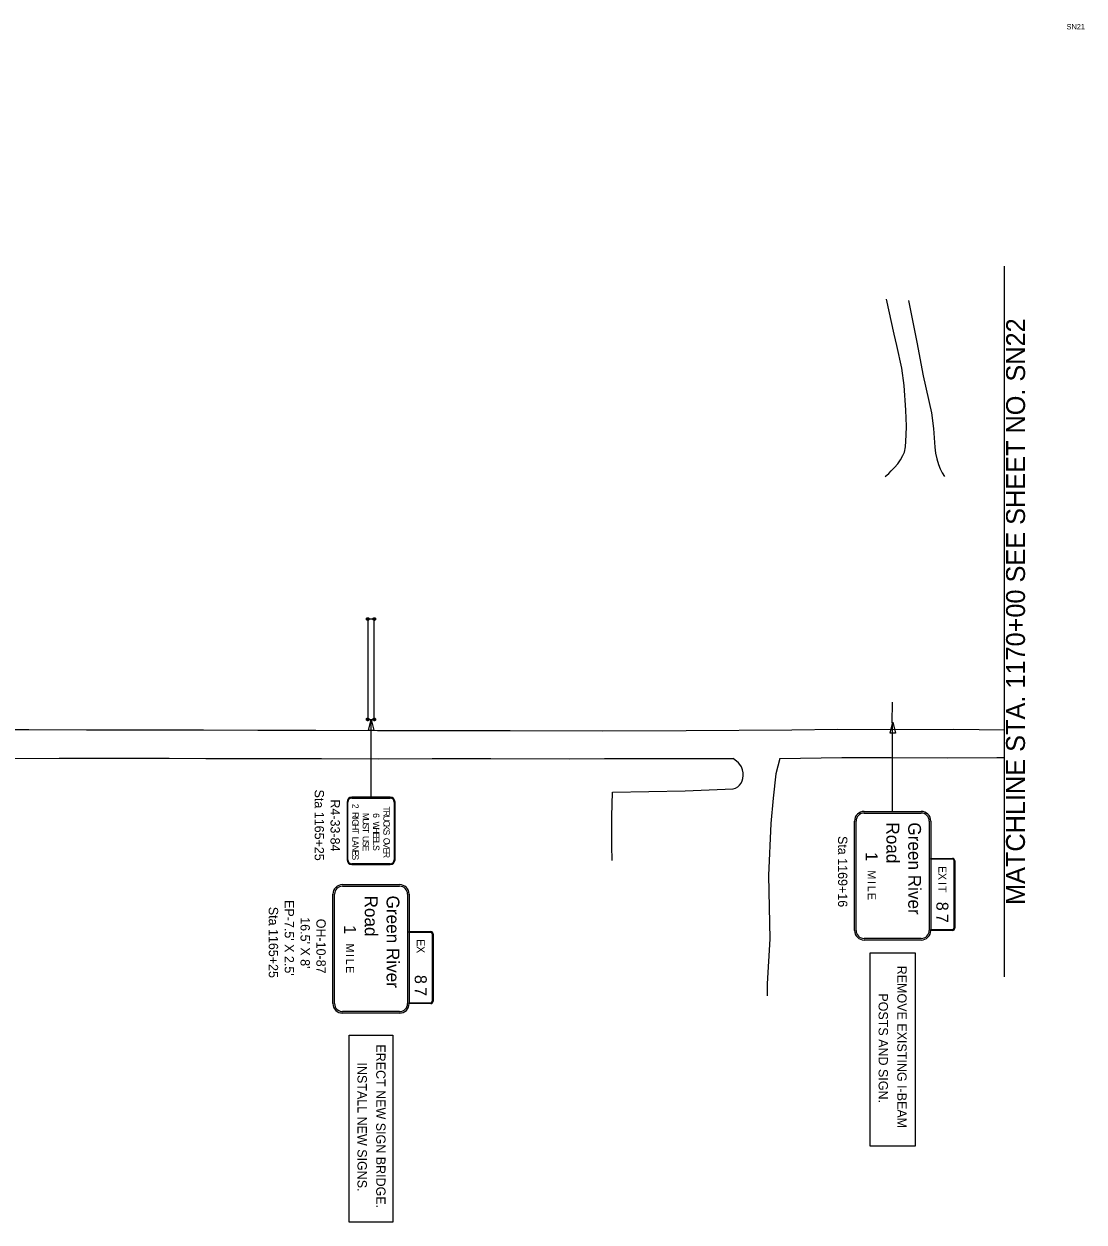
# Model space of a CAD drawing. Extents: x 1738684 to 1740273, y 1165576 to 1166490.
# Drawn here: x 1739479 to 1740273, y 1165592 to 1166490 of the extents above; entities that cross this region are included whole.
import ezdxf

# ---------------------------------------------------------------- set-up
doc = ezdxf.new("R2010")
doc.units = 0
for name, color, linetype in [('RD_EX_Driveway', 7, 'Continuous'), ('RD_EX_Road', 7, 'Continuous'), ('RD_SHT_MatchLine', 7, 'Continuous'), ('RD_SHT_TX', 7, 'Continuous'), ('SN_P_Signs', 7, 'Continuous')]:
    doc.layers.add(name, color=color, linetype=linetype)

msp = doc.modelspace()

# ---------------------------------------------------------------- linework, layer by layer
at = {"layer": 'RD_EX_Driveway'}
for points in [[(1740124.3, 1166150.79), (1740126.88, 1166153.21), (1740128.62, 1166155.12), (1740131.31, 1166157.59), (1740133.71, 1166160.34), (1740135.8, 1166163.33), (1740137.56, 1166166.52), (1740138.63, 1166169), (1740139.39, 1166173.21), (1740139.88, 1166181.79), (1740140.08, 1166188.6), (1740139.67, 1166200.6), (1740138.43, 1166219.04), (1740136.79, 1166232.06), (1740133.05, 1166248.97), (1740130.97, 1166257.45), (1740125.25, 1166283.83)], [(1740141.68, 1166282.68), (1740147.89, 1166251.53), (1740152.64, 1166226.36), (1740158.84, 1166198.47), (1740160.4, 1166186.89), (1740161.51, 1166172.79), (1740161.99, 1166168.39), (1740162.85, 1166164.05), (1740164.1, 1166159.81), (1740165.34, 1166156.58), (1740166.9, 1166153.51), (1740168.71, 1166150.79)]]:
    msp.add_lwpolyline(points, dxfattribs=at)
at = {"layer": 'RD_EX_Road'}
for points in [[(1739438.73, 1165961.23), (1739482.2, 1165961.17), (1739525.52, 1165960.92), (1739569.49, 1165960.93), (1739613.16, 1165961.06), (1739653.93, 1165960.81), (1739697.41, 1165960.69), (1739743.53, 1165960.46), (1739801.27, 1165960.46), (1739843.11, 1165960.51), (1739912.34, 1165960.31), (1739974.95, 1165960.36), (1740054.2, 1165960.92), (1740088.36, 1165961.42), (1740131.15, 1165961.18), (1740175.74, 1165961.39), (1740213.73, 1165961.1)], [(1739459.48, 1165939.5), (1739504.95, 1165939.79), (1739528.09, 1165939.84), (1739548.18, 1165939.78), (1739587.4, 1165939.65), (1739614.91, 1165939.48), (1739637.66, 1165939.49), (1739674.67, 1165939.42), (1739701.63, 1165939.38), (1739744.03, 1165939.26), (1739784.65, 1165939.45), (1739828.6, 1165939.52), (1739887.88, 1165939.19), (1739913.86, 1165939.4), (1739956.57, 1165939.5), (1740000.31, 1165939.39), (1740010.26, 1165939.42)], [(1739919.5, 1165863.11), (1739919.27, 1165874.13), (1739919.22, 1165895.91), (1739919.69, 1165914.25), (1739974.21, 1165915.27), (1740010.18, 1165916.63), (1740012, 1165917.21), (1740013.66, 1165918.14), (1740015.09, 1165919.4), (1740016.24, 1165920.92), (1740017.05, 1165922.65), (1740017.48, 1165924.41), (1740017.8, 1165926.63), (1740017.73, 1165928.87), (1740017.28, 1165931.06), (1740016.44, 1165933.14), (1740015.25, 1165935.04), (1740014.34, 1165936.13), (1740010.26, 1165939.42)], [(1740045.27, 1165939.54), (1740042.13, 1165928), (1740040.27, 1165909.67), (1740038.6, 1165890.89), (1740036.74, 1165851.82), (1740037.76, 1165804.35), (1740035.82, 1165770.69), (1740035.65, 1165761.7)], [(1740045.27, 1165939.54), (1740091.68, 1165940.16), (1740128.58, 1165940.15), (1740170.89, 1165940.11), (1740207.97, 1165940.27), (1740213.73, 1165940.27)]]:
    msp.add_lwpolyline(points, dxfattribs=at)
at = {"layer": 'RD_SHT_MatchLine'}
msp.add_lwpolyline([(1740213.73, 1165775.92), (1740213.73, 1166044.04), (1740213.73, 1166308.6)], dxfattribs=at)
at = {"layer": 'SN_P_Signs'}
for p, q in [((1739735.55, 1166044.75), (1739736.96, 1166043.33)), ((1739735.55, 1166043.34), (1739736.96, 1166044.75)), ((1739741.21, 1166044.04), (1739736.26, 1166044.04)), ((1739736.26, 1166044.04), (1739736.26, 1165968.79)), ((1739740.51, 1166044.75), (1739741.92, 1166043.33)), ((1739740.51, 1166043.34), (1739741.92, 1166044.75)), ((1739741.21, 1165968.79), (1739741.21, 1166044.04)), ((1740129.46, 1165966.18), (1740129.66, 1165981.72)), ((1739735.55, 1165969.5), (1739736.96, 1165968.08)), ((1739735.55, 1165968.09), (1739736.96, 1165969.5)), ((1739736.26, 1165968.79), (1739741.21, 1165968.79)), ((1739738.73, 1165910.44), (1739738.73, 1165968.79)), ((1739740.51, 1165969.5), (1739741.92, 1165968.08)), ((1739740.51, 1165968.09), (1739741.92, 1165969.5)), ((1740129.82, 1165899.83), (1740129.82, 1165966.65)), ((1740113.01, 1165648.89), (1740113.01, 1165793.91)), ((1740113.01, 1165793.91), (1740146.63, 1165793.91)), ((1740146.63, 1165793.91), (1740146.63, 1165648.89)), ((1739722.33, 1165592.05), (1739722.33, 1165732)), ((1739722.33, 1165732), (1739755.14, 1165732)), ((1739755.14, 1165732), (1739755.14, 1165592.05)), ((1740146.63, 1165648.89), (1740113.01, 1165648.89)), ((1739755.14, 1165592.05), (1739722.33, 1165592.05))]:
    msp.add_line(p, q, dxfattribs=at)
for points in [[(1739736.26, 1166043.04), (1739736.09, 1166043.06), (1739735.93, 1166043.1), (1739735.77, 1166043.16), (1739735.64, 1166043.26), (1739735.51, 1166043.37), (1739735.41, 1166043.5), (1739735.34, 1166043.65), (1739735.28, 1166043.81), (1739735.26, 1166043.97), (1739735.26, 1166044.14), (1739735.29, 1166044.31), (1739735.35, 1166044.46), (1739735.43, 1166044.61), (1739735.54, 1166044.74), (1739735.66, 1166044.85), (1739735.81, 1166044.93), (1739735.96, 1166045), (1739736.12, 1166045.03), (1739736.26, 1166045.04)], [(1739736.26, 1166045.04), (1739736.42, 1166045.03), (1739736.59, 1166044.99), (1739736.74, 1166044.92), (1739736.88, 1166044.83), (1739737, 1166044.71), (1739737.1, 1166044.58), (1739737.18, 1166044.43), (1739737.23, 1166044.27), (1739737.25, 1166044.11), (1739737.25, 1166043.94), (1739737.22, 1166043.78), (1739737.16, 1166043.62), (1739737.08, 1166043.47), (1739736.98, 1166043.35), (1739736.85, 1166043.24), (1739736.71, 1166043.15), (1739736.55, 1166043.09), (1739736.39, 1166043.05), (1739736.26, 1166043.04)], [(1739741.21, 1166043.04), (1739741.05, 1166043.06), (1739740.88, 1166043.1), (1739740.73, 1166043.16), (1739740.59, 1166043.26), (1739740.47, 1166043.37), (1739740.37, 1166043.5), (1739740.29, 1166043.65), (1739740.24, 1166043.81), (1739740.21, 1166043.97), (1739740.22, 1166044.14), (1739740.25, 1166044.31), (1739740.31, 1166044.46), (1739740.39, 1166044.61), (1739740.49, 1166044.74), (1739740.62, 1166044.85), (1739740.76, 1166044.93), (1739740.92, 1166045), (1739741.08, 1166045.03), (1739741.21, 1166045.04)], [(1739741.21, 1166045.04), (1739741.38, 1166045.03), (1739741.54, 1166044.99), (1739741.69, 1166044.92), (1739741.83, 1166044.83), (1739741.95, 1166044.71), (1739742.06, 1166044.58), (1739742.13, 1166044.43), (1739742.19, 1166044.27), (1739742.21, 1166044.11), (1739742.21, 1166043.94), (1739742.18, 1166043.78), (1739742.12, 1166043.62), (1739742.04, 1166043.47), (1739741.93, 1166043.35), (1739741.8, 1166043.24), (1739741.66, 1166043.15), (1739741.51, 1166043.09), (1739741.35, 1166043.05), (1739741.21, 1166043.04)], [(1739736.26, 1165967.79), (1739736.09, 1165967.81), (1739735.93, 1165967.85), (1739735.77, 1165967.91), (1739735.64, 1165968.01), (1739735.51, 1165968.12), (1739735.41, 1165968.25), (1739735.34, 1165968.4), (1739735.28, 1165968.56), (1739735.26, 1165968.72), (1739735.26, 1165968.89), (1739735.29, 1165969.06), (1739735.35, 1165969.21), (1739735.43, 1165969.36), (1739735.54, 1165969.49), (1739735.66, 1165969.6), (1739735.81, 1165969.68), (1739735.96, 1165969.75), (1739736.12, 1165969.78), (1739736.26, 1165969.79)], [(1739736.26, 1165969.79), (1739736.42, 1165969.78), (1739736.59, 1165969.74), (1739736.74, 1165969.67), (1739736.88, 1165969.58), (1739737, 1165969.46), (1739737.1, 1165969.33), (1739737.18, 1165969.18), (1739737.23, 1165969.02), (1739737.25, 1165968.86), (1739737.25, 1165968.69), (1739737.22, 1165968.53), (1739737.16, 1165968.37), (1739737.08, 1165968.22), (1739736.98, 1165968.1), (1739736.85, 1165967.99), (1739736.71, 1165967.9), (1739736.55, 1165967.84), (1739736.39, 1165967.8), (1739736.26, 1165967.79)], [(1739741.21, 1165967.79), (1739741.05, 1165967.81), (1739740.88, 1165967.85), (1739740.73, 1165967.91), (1739740.59, 1165968.01), (1739740.47, 1165968.12), (1739740.37, 1165968.25), (1739740.29, 1165968.4), (1739740.24, 1165968.56), (1739740.21, 1165968.72), (1739740.22, 1165968.89), (1739740.25, 1165969.06), (1739740.31, 1165969.21), (1739740.39, 1165969.36), (1739740.49, 1165969.49), (1739740.62, 1165969.6), (1739740.76, 1165969.68), (1739740.92, 1165969.75), (1739741.08, 1165969.78), (1739741.21, 1165969.79)], [(1739741.21, 1165969.79), (1739741.38, 1165969.78), (1739741.54, 1165969.74), (1739741.69, 1165969.67), (1739741.83, 1165969.58), (1739741.95, 1165969.46), (1739742.06, 1165969.33), (1739742.13, 1165969.18), (1739742.19, 1165969.02), (1739742.21, 1165968.86), (1739742.21, 1165968.69), (1739742.18, 1165968.53), (1739742.12, 1165968.37), (1739742.04, 1165968.22), (1739741.93, 1165968.1), (1739741.8, 1165967.99), (1739741.66, 1165967.9), (1739741.51, 1165967.84), (1739741.35, 1165967.8), (1739741.21, 1165967.79)], [(1739720.73, 1165906.84), (1739720.73, 1165863.64)], [(1739721.33, 1165863.64), (1739721.33, 1165906.84)], [(1739753.13, 1165910.44), (1739724.33, 1165910.44)], [(1739724.33, 1165909.84), (1739753.13, 1165909.84)], [(1739756.13, 1165906.84), (1739756.13, 1165863.64)], [(1739756.73, 1165863.64), (1739756.73, 1165906.84)], [(1740108.43, 1165899.83), (1740151.21, 1165899.83)], [(1740108.43, 1165898.63), (1740151.21, 1165898.63)], [(1740101.23, 1165810.64), (1740101.23, 1165892.63)], [(1740102.43, 1165810.64), (1740102.43, 1165892.63)], [(1740157.21, 1165892.63), (1740157.21, 1165810.64)], [(1740158.41, 1165892.63), (1740158.41, 1165810.64)], [(1739753.13, 1165860.64), (1739724.33, 1165860.64)], [(1739724.33, 1165860.04), (1739753.13, 1165860.04)], [(1740174.61, 1165864.04), (1740158.41, 1165864.04), (1740158.41, 1165864.64), (1740174.61, 1165864.64)], [(1740175.81, 1165812.44), (1740175.81, 1165862.84)], [(1740176.41, 1165862.84), (1740176.41, 1165812.44)], [(1739717.35, 1165844.98), (1739760.12, 1165844.98)], [(1739717.35, 1165843.78), (1739760.12, 1165843.78)], [(1739710.15, 1165755.79), (1739710.15, 1165837.78)], [(1739711.35, 1165755.79), (1739711.35, 1165837.78)], [(1739766.12, 1165837.78), (1739766.12, 1165755.79)], [(1739767.32, 1165837.78), (1739767.32, 1165755.79)], [(1739783.52, 1165809.19), (1739767.32, 1165809.19), (1739767.32, 1165809.79), (1739783.52, 1165809.79)], [(1739784.72, 1165757.59), (1739784.72, 1165807.99)], [(1739785.32, 1165807.99), (1739785.32, 1165757.59)], [(1740151.21, 1165804.64), (1740108.43, 1165804.64)], [(1740151.21, 1165803.44), (1740108.43, 1165803.44)], [(1740174.61, 1165810.64), (1740158.41, 1165810.64), (1740158.41, 1165811.24)], [(1740158.41, 1165811.24), (1740174.61, 1165811.24)], [(1739760.12, 1165749.79), (1739717.35, 1165749.79)], [(1739783.52, 1165755.79), (1739767.32, 1165755.79), (1739767.32, 1165756.39)], [(1739767.32, 1165756.39), (1739783.52, 1165756.39)], [(1739760.12, 1165748.59), (1739717.35, 1165748.59)]]:
    msp.add_lwpolyline(points, dxfattribs=at)
for points in [[(1739736.82, 1165960.57), (1739738.78, 1165968.79), (1739740.92, 1165960.61)], [(1740127.9, 1165958.43), (1740129.86, 1165966.65), (1740132.01, 1165958.47)]]:
    msp.add_lwpolyline(points, close=True, dxfattribs=at)
for centre, radius, start, end in [((1739724.33, 1165906.84), 3.6, 90, 180), ((1739724.33, 1165906.84), 3, 90, 180), ((1739753.13, 1165906.84), 3.6, 360, 90), ((1739753.13, 1165906.84), 3, 360, 90), ((1740108.43, 1165892.63), 7.2, 90, 180), ((1740108.43, 1165892.63), 6, 90, 180), ((1740151.21, 1165892.63), 7.2, 360, 90), ((1740151.21, 1165892.63), 6, 360, 90), ((1739724.33, 1165863.64), 3.6, 180, 270), ((1739724.33, 1165863.64), 3, 180, 270), ((1739753.13, 1165863.64), 3.6, 270, 360), ((1739753.13, 1165863.64), 3, 270, 360), ((1740174.61, 1165862.84), 1.8, 360, 90), ((1740174.61, 1165862.84), 1.2, 360, 90), ((1739717.35, 1165837.78), 7.2, 90, 180), ((1739717.35, 1165837.78), 6, 90, 180), ((1739760.12, 1165837.78), 7.2, 360, 90), ((1739760.12, 1165837.78), 6, 360, 90), ((1740174.61, 1165812.44), 1.8, 270, 360), ((1740174.61, 1165812.44), 1.2, 270, 360), ((1739783.52, 1165807.99), 1.8, 360, 90), ((1739783.52, 1165807.99), 1.2, 360, 90), ((1740108.43, 1165810.64), 7.2, 180, 270), ((1740108.43, 1165810.64), 6, 180, 270), ((1740151.21, 1165810.64), 6, 270, 360), ((1740151.21, 1165810.64), 7.2, 270, 360), ((1739717.35, 1165755.79), 7.2, 180, 270), ((1739717.35, 1165755.79), 6, 180, 270), ((1739760.12, 1165755.79), 6, 270, 360), ((1739760.12, 1165755.79), 7.2, 270, 360), ((1739783.52, 1165757.59), 1.8, 270, 360), ((1739783.52, 1165757.59), 1.2, 270, 360)]:
    msp.add_arc(centre, radius, start, end, dxfattribs=at)

# ---------------------------------------------------------------- texts
at = {"layer": 'RD_SHT_TX'}
msp.add_text('SN21', height=4, dxfattribs=at).set_placement((1740260.19, 1166486))
msp.add_text('MATCHLINE STA. 1170+00 SEE SHEET NO. SN22', height=14.1726, rotation=89.98556, dxfattribs=at).set_placement((1740228.98, 1165829.69))
at = {"layer": 'SN_P_Signs'}
for s, height, rotation, p in [('Sta 1165+25', 7, 270.00008, (1739696.46, 1165916.21)), ('R4-33-84', 7, 270.00008, (1739708.36, 1165908.83)), ('2', 4.8, 270, (1739724.63, 1165905.52)), ('T', 4.8, 270, (1739748.03, 1165903.6)), ('G', 4.8, 270, (1739724.63, 1165893.98)), ('R', 4.8, 270, (1739724.63, 1165899.3)), ('I', 4.8, 270, (1739724.63, 1165895.66)), ('U', 4.8, 270, (1739732.43, 1165894.55)), ('M', 4.8, 270, (1739732.43, 1165898.67)), ('6', 4.8, 270, (1739740.23, 1165898.5)), ('U', 4.8, 270, (1739748.03, 1165896.76)), ('R', 4.8, 270, (1739748.03, 1165900.39)), ('H', 4.8, 270, (1739724.63, 1165890.34)), ('T', 4.8, 270, (1739724.63, 1165886.9)), ('S', 4.8, 270, (1739732.43, 1165890.91)), ('T', 4.8, 270, (1739732.43, 1165887.47)), ('W', 4.8, 270, (1739740.23, 1165892.28)), ('H', 4.8, 270, (1739740.23, 1165887.86)), ('C', 4.8, 270, (1739748.03, 1165893.12)), ('S', 4.8, 270, (1739748.03, 1165886.25)), ('K', 4.8, 270, (1739748.03, 1165889.69)), ('Road', 9.6, 270, (1740125.15, 1165891.59)), ('Green River', 9.6, 270, (1740141.47, 1165891.59)), ('L', 4.8, 270, (1739724.63, 1165880.9)), ('A', 4.8, 270, (1739724.63, 1165878.23)), ('U', 4.8, 270, (1739732.43, 1165881.47)), ('S', 4.8, 270, (1739732.43, 1165877.84)), ('E', 4.8, 270, (1739740.23, 1165884.23)), ('E', 4.8, 270, (1739740.23, 1165881.02)), ('L', 4.8, 270, (1739740.23, 1165877.81)), ('O', 4.8, 270, (1739748.03, 1165880.03)), ('V', 4.8, 270, (1739748.03, 1165876.44)), ('Sta 1169+16', 7, 270.00008, (1740088.86, 1165881.38)), ('S', 4.8, 270, (1739724.63, 1165867.58)), ('N', 4.8, 270, (1739724.63, 1165874.42)), ('E', 4.8, 270, (1739724.63, 1165870.79)), ('E', 4.8, 270, (1739732.43, 1165874.2)), ('S', 4.8, 270, (1739740.23, 1165874.6)), ('E', 4.8, 270, (1739748.03, 1165872.7)), ('R', 4.8, 270, (1739748.03, 1165869.49)), ('1', 9, 270, (1740109.63, 1165869.36)), ('E', 6, 270, (1740164.11, 1165858.91)), ('M', 6, 270, (1740111.13, 1165855.62)), ('X', 6, 270, (1740164.11, 1165853.76)), ('I', 6, 270, (1740111.13, 1165847.76)), ('L', 6, 270, (1740111.13, 1165844.16)), ('I', 6, 270, (1740164.11, 1165846.94)), ('T', 6, 270, (1740164.11, 1165843.96)), ("EP-7.5' X 2.5'", 7, 270.00008, (1739673.97, 1165833.36)), ('Road', 9.6, 270, (1739734.07, 1165836.74)), ('Green River', 9.6, 270, (1739750.39, 1165836.74)), ('E', 6, 270, (1740111.13, 1165838.74)), ('8', 9, 270, (1740162.61, 1165832.09)), ('Sta 1165+25', 7, 270.00008, (1739662.07, 1165828.34)), ('7', 9, 270, (1740162.61, 1165822.99)), ("16.5' X 8'", 7, 270.00008, (1739685.87, 1165820.52)), ('OH-10-87', 7, 270.00008, (1739697.77, 1165819.36)), ('1', 9, 270, (1739718.55, 1165814.51)), ('E', 6, 270, (1739773.02, 1165804.06)), ('M', 6, 270, (1739720.05, 1165800.77)), ('X', 6, 270, (1739773.02, 1165798.91)), ('I', 6, 270, (1739720.05, 1165792.91)), ('L', 6, 270, (1739720.05, 1165789.31)), ('E', 6, 270, (1739720.05, 1165783.89)), ('8', 9, 270, (1739771.52, 1165777.24)), ('REMOVE EXISTING I-BEAM', 6.9998, 270.00008, (1740133.27, 1165784.16)), ('7', 9, 270, (1739771.52, 1165768.13)), ('POSTS AND SIGN.', 6.9998, 270.00008, (1740119.27, 1165763.45)), ('ERECT NEW SIGN BRIDGE.', 6.9998, 270.00008, (1739742.59, 1165725.22)), ('INSTALL NEW SIGNS.', 6.9998, 270.00008, (1739728.59, 1165711.64))]:
    msp.add_text(s, height=height, rotation=rotation, dxfattribs=at).set_placement(p)

doc.saveas('drawing.dxf')
